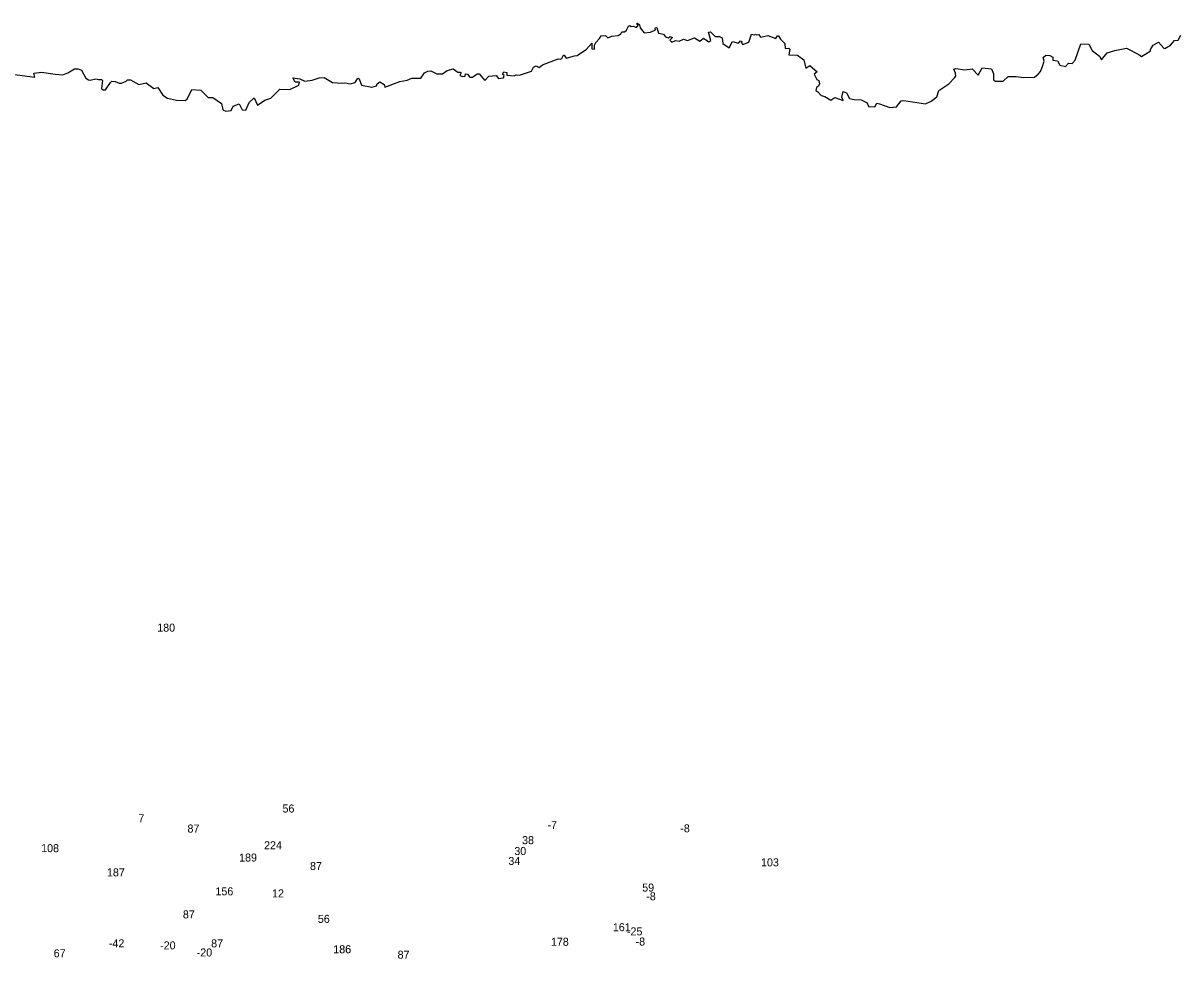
# Model space of a CAD drawing. Extents: x -788870 to -783053, y -967261 to -964403.
# Drawn here: x -787389 to -785943, y -965596 to -964427 of the extents above; entities that cross this region are included whole.
import ezdxf

# ---------------------------------------------------------------- set-up
doc = ezdxf.new("R2010")
doc.units = 0
doc.layers.add('Vrstva 13', color=7, linetype='Continuous')
doc.layers.add('Vrstva 15', color=7, linetype='Continuous')

msp = doc.modelspace()

# ---------------------------------------------------------------- linework, layer by layer
at = {"layer": 'Vrstva 13'}
for p, q in [((-786635.28, -964435.87), (-786632.81, -964430.8)), ((-786632.81, -964430.8), (-786631.37, -964429.93)), ((-786631.37, -964429.93), (-786629.34, -964431.52)), ((-786629.34, -964431.52), (-786626.44, -964430.73)), ((-786626.44, -964430.73), (-786622.68, -964432.68)), ((-786622.75, -964428.19), (-786621.52, -964427.18)), ((-786620.94, -964429.71), (-786622.75, -964428.19)), ((-786622.68, -964432.68), (-786620.94, -964429.71)), ((-786621.52, -964427.18), (-786618.91, -964429.35)), ((-786618.91, -964429.35), (-786618.26, -964432.9)), ((-786673.52, -964451.3), (-786669.1, -964446.23)), ((-786669.1, -964446.23), (-786666.78, -964443.04)), ((-786666.78, -964443.04), (-786661.71, -964442.39)), ((-786661.71, -964442.39), (-786658.46, -964445.57)), ((-786658.46, -964445.57), (-786653.75, -964443.4)), ((-786653.75, -964443.4), (-786645.64, -964442.46)), ((-786645.64, -964442.46), (-786642.24, -964440.5)), ((-786642.24, -964440.5), (-786641.37, -964437.82)), ((-786641.37, -964437.82), (-786637.81, -964437.82)), ((-786637.81, -964437.82), (-786635.28, -964435.87)), ((-786618.26, -964432.9), (-786613.26, -964439.2)), ((-786613.26, -964439.2), (-786605.15, -964438.33)), ((-786605.15, -964438.33), (-786599.14, -964435.51)), ((-786599.65, -964433.04), (-786597.33, -964432.46)), ((-786599.14, -964435.51), (-786599.65, -964433.04)), ((-786597.33, -964432.46), (-786595.16, -964439.85)), ((-786595.16, -964439.85), (-786589.29, -964440.72)), ((-786589.29, -964440.72), (-786586.69, -964444.13)), ((-786586.69, -964444.13), (-786582.85, -964445.65)), ((-786582.85, -964445.65), (-786580.67, -964443.91)), ((-786578, -964444.92), (-786581.33, -964448.33)), ((-786580.67, -964443.91), (-786578, -964444.92)), ((-786559.1, -964448.91), (-786550.26, -964445.51)), ((-786550.26, -964445.51), (-786543.82, -964449.56)), ((-786543.82, -964449.56), (-786539.11, -964445.94)), ((-786539.11, -964445.94), (-786532.52, -964450.43)), ((-786533.1, -964438.55), (-786530.42, -964438.04)), ((-786529.91, -964448.84), (-786533.1, -964438.55)), ((-786530.42, -964438.04), (-786524.41, -964443.98)), ((-786524.41, -964443.98), (-786519.05, -964443.98)), ((-786519.05, -964443.98), (-786516.01, -964445.29)), ((-786516.01, -964445.29), (-786514.85, -964452.68)), ((-786482.33, -964451.09), (-786479, -964440.8)), ((-786479, -964440.8), (-786475.67, -964441.6)), ((-786475.67, -964441.6), (-786473.86, -964440.73)), ((-786473.86, -964440.73), (-786473.5, -964441.74)), ((-786473.5, -964441.74), (-786470.09, -964441.16)), ((-786470.09, -964441.16), (-786468.07, -964444.78)), ((-786468.07, -964444.78), (-786458.94, -964442.39)), ((-786458.94, -964442.39), (-786448.73, -964446.38)), ((-786448.73, -964446.38), (-786446.85, -964442.9)), ((-786446.85, -964442.9), (-786445.33, -964442.9)), ((-786445.33, -964442.9), (-786442.94, -964447.32)), ((-785946.35, -964448.35), (-785942.82, -964442.17)), ((-786697.13, -964467.59), (-786685.25, -964459.7)), ((-786685.25, -964459.7), (-786678.81, -964452.02)), ((-786678.81, -964452.02), (-786678.74, -964459.33)), ((-786678.74, -964459.33), (-786675.48, -964459.77)), ((-786675.48, -964459.77), (-786675.47, -964454.85)), ((-786675.47, -964454.85), (-786673.52, -964451.3)), ((-786581.33, -964448.33), (-786578.5, -964450.86)), ((-786578.5, -964450.86), (-786574.02, -964448.69)), ((-786574.02, -964448.69), (-786569.53, -964449.49)), ((-786569.53, -964449.49), (-786564.1, -964447.32)), ((-786564.1, -964447.32), (-786559.1, -964448.91)), ((-786532.52, -964450.43), (-786529.91, -964448.84)), ((-786514.85, -964452.68), (-786507.24, -964457.96)), ((-786507.24, -964457.96), (-786502.83, -964449.99)), ((-786502.83, -964449.99), (-786495.37, -964452.1)), ((-786495.37, -964452.1), (-786492.76, -964449.21)), ((-786492.76, -964449.21), (-786491.17, -964450.07)), ((-786491.17, -964450.07), (-786492.04, -964451.52)), ((-786492.04, -964451.52), (-786490.15, -964453.99)), ((-786490.15, -964453.99), (-786482.33, -964451.09)), ((-786442.94, -964447.32), (-786437.72, -964452.39)), ((-786437.72, -964452.39), (-786437.22, -964458.98)), ((-786437.22, -964458.98), (-786432.73, -964458.26)), ((-786432.73, -964458.26), (-786431.28, -964459.49)), ((-786431.28, -964459.49), (-786432.72, -964466.74)), ((-786074.99, -964473.33), (-786067.74, -964453.19)), ((-786067.74, -964453.19), (-786057.75, -964453.61)), ((-786057.75, -964453.61), (-786053.69, -964461.15)), ((-786025.3, -964461.15), (-786010.82, -964458.54)), ((-786010.82, -964458.54), (-785995.18, -964466.36)), ((-785981.23, -964462.26), (-785980.13, -964459.17)), ((-785980.13, -964459.17), (-785977.48, -964454.75)), ((-785977.48, -964454.75), (-785970.63, -964451)), ((-785970.63, -964451), (-785964.23, -964458.51)), ((-785964.23, -964458.51), (-785962.91, -964458.95)), ((-785962.91, -964458.95), (-785955.84, -964454.75)), ((-785955.84, -964454.75), (-785950.77, -964448.79)), ((-785950.77, -964448.79), (-785946.35, -964448.35)), ((-786740.44, -964479.39), (-786720.52, -964471.79)), ((-786720.52, -964471.79), (-786717.77, -964472.16)), ((-786717.77, -964472.16), (-786716.03, -964471.14)), ((-786716.03, -964471.14), (-786714.07, -964467.09)), ((-786714.07, -964467.09), (-786713.21, -964467.23)), ((-786713.21, -964467.23), (-786710.82, -964470.78)), ((-786710.82, -964470.78), (-786700.39, -964467.81)), ((-786700.39, -964467.81), (-786697.13, -964467.59)), ((-786432.72, -964466.74), (-786421.64, -964466.96)), ((-786421.64, -964466.96), (-786413.89, -964472.97)), ((-786413.89, -964472.97), (-786411.5, -964483.18)), ((-786115.54, -964481.45), (-786113.66, -964474.64)), ((-786114.82, -964470.15), (-786111.34, -964466.96)), ((-786113.66, -964474.64), (-786114.82, -964470.15)), ((-786111.34, -964466.96), (-786106.42, -964467.39)), ((-786106.42, -964467.39), (-786102.8, -964469.71)), ((-786102.8, -964469.71), (-786102.8, -964473.48)), ((-786102.8, -964473.48), (-786096.86, -964474.35)), ((-786096.86, -964474.35), (-786093.82, -964479.42)), ((-786078.46, -964477.38), (-786074.99, -964473.33)), ((-786053.69, -964461.15), (-786044.42, -964468.39)), ((-786044.42, -964468.39), (-786041.82, -964473.03)), ((-786041.82, -964473.03), (-786034.86, -964464.34)), ((-786034.86, -964464.34), (-786025.3, -964461.15)), ((-785995.18, -964466.36), (-785991.99, -964468.97)), ((-785991.99, -964468.97), (-785981.23, -964462.26)), ((-787375.53, -964489.54), (-787365.83, -964488.23)), ((-787374.37, -964494.75), (-787375.53, -964489.54)), ((-787365.83, -964488.23), (-787358.01, -964489.54)), ((-787358.01, -964489.54), (-787349.03, -964490.84)), ((-787339.32, -964491.71), (-787333.24, -964489.39)), ((-787333.24, -964489.39), (-787324.98, -964484.32)), ((-787324.98, -964484.32), (-787320.35, -964484.18)), ((-787320.35, -964484.18), (-787316.15, -964485.92)), ((-787316.15, -964485.92), (-787310.65, -964495.77)), ((-786892.23, -964495.76), (-786887.88, -964489.39)), ((-786887.88, -964489.39), (-786883.39, -964487.21)), ((-786883.39, -964487.21), (-786879.77, -964486.63)), ((-786879.77, -964486.63), (-786872.24, -964490.25)), ((-786865.28, -964490.26), (-786859.34, -964486.2)), ((-786859.34, -964486.2), (-786851.67, -964484.17)), ((-786851.67, -964484.17), (-786849.06, -964486.49)), ((-786849.06, -964486.49), (-786846.16, -964488.38)), ((-786846.16, -964488.38), (-786843.27, -964488.38)), ((-786841.96, -964489.24), (-786843.41, -964492.43)), ((-786843.27, -964488.38), (-786841.96, -964489.24)), ((-786790.41, -964490.84), (-786788.52, -964487.8)), ((-786788.52, -964487.8), (-786784.9, -964488.66)), ((-786784.9, -964488.66), (-786784.68, -964492)), ((-786768.97, -964492.29), (-786754.05, -964486.93)), ((-786754.05, -964486.93), (-786751.66, -964482.15)), ((-786751.66, -964482.15), (-786748.19, -964480.26)), ((-786748.19, -964480.26), (-786744.57, -964482.58)), ((-786744.57, -964482.58), (-786740.44, -964479.39)), ((-786411.5, -964483.18), (-786406.29, -964479.92)), ((-786406.29, -964479.92), (-786396.95, -964487.75)), ((-786396.95, -964487.75), (-786401, -964490.86)), ((-786226.49, -964484.63), (-786223.88, -964483.91)), ((-786224.31, -964489.56), (-786226.49, -964484.63)), ((-786223.88, -964493.32), (-786224.31, -964489.56)), ((-786223.88, -964483.91), (-786212.58, -964485.36)), ((-786212.58, -964485.36), (-786203.46, -964484.2)), ((-786203.46, -964484.2), (-786196.22, -964492.31)), ((-786196.22, -964492.31), (-786191, -964482.89)), ((-786191, -964482.89), (-786179.41, -964484.2)), ((-786179.41, -964484.2), (-786176.95, -964490.57)), ((-786121.04, -964490.72), (-786118.15, -964487.39)), ((-786118.15, -964487.39), (-786115.54, -964481.45)), ((-786093.82, -964479.42), (-786086.72, -964481.16)), ((-786086.72, -964481.16), (-786083.1, -964476.95)), ((-786083.1, -964476.95), (-786078.46, -964477.38)), ((-787402.61, -964490.99), (-787374.37, -964494.75)), ((-787349.03, -964490.84), (-787339.32, -964491.71)), ((-787310.65, -964495.77), (-787307.6, -964497.8)), ((-787307.6, -964497.8), (-787305.43, -964498.23)), ((-787305.43, -964498.23), (-787298.48, -964496.49)), ((-787298.48, -964496.49), (-787295, -964497.65)), ((-787295, -964497.65), (-787291.24, -964497.65)), ((-787289.79, -964498.95), (-787291.38, -964508.66)), ((-787291.24, -964497.65), (-787289.79, -964498.95)), ((-787286.17, -964510.4), (-787280.09, -964501.13)), ((-787280.09, -964501.13), (-787278.2, -964499.53)), ((-787278.2, -964499.53), (-787274.29, -964500.11)), ((-787274.29, -964500.11), (-787268.93, -964502)), ((-787268.93, -964502), (-787266.04, -964502.29)), ((-787266.04, -964502.29), (-787260.53, -964499.53)), ((-787260.53, -964499.53), (-787258.65, -964497.94)), ((-787258.65, -964497.94), (-787255.03, -964498.08)), ((-787255.03, -964498.08), (-787244.46, -964503.88)), ((-787244.46, -964503.88), (-787235.48, -964501.71)), ((-787235.48, -964501.71), (-787225.92, -964508.66)), ((-787049.37, -964500.68), (-787052.26, -964495.32)), ((-787052.26, -964495.32), (-787043.28, -964496.77)), ((-787043.72, -964500.83), (-787049.37, -964500.68)), ((-787044.88, -964504.74), (-787043.72, -964500.83)), ((-787043.28, -964496.77), (-787037.35, -964499.52)), ((-787037.35, -964499.52), (-787028.08, -964498.36)), ((-787028.08, -964498.36), (-787019.1, -964495.61)), ((-787019.1, -964495.61), (-787013.16, -964495.18)), ((-787013.16, -964495.18), (-787002.73, -964501.26)), ((-787002.73, -964501.26), (-786990.28, -964502.13)), ((-786990.28, -964502.13), (-786986.37, -964501.55)), ((-786986.37, -964501.55), (-786980.58, -964503)), ((-786980.58, -964503), (-786974.2, -964501.12)), ((-786974.2, -964501.12), (-786971.16, -964495.9)), ((-786971.16, -964495.9), (-786969.13, -964496.77)), ((-786969.13, -964496.77), (-786966.24, -964504.45)), ((-786947.84, -964505.32), (-786946.97, -964503.14)), ((-786946.97, -964503.14), (-786943.64, -964500.25)), ((-786943.64, -964500.25), (-786938.28, -964503.87)), ((-786938.28, -964503.87), (-786937.13, -964507.21)), ((-786937.13, -964507.21), (-786918.3, -964500.11)), ((-786918.3, -964500.11), (-786909.32, -964498.51)), ((-786909.32, -964498.51), (-786903.38, -964495.76)), ((-786903.38, -964495.76), (-786892.23, -964495.76)), ((-786872.24, -964490.25), (-786865.28, -964490.26)), ((-786843.41, -964492.43), (-786839.79, -964493.88)), ((-786839.79, -964493.88), (-786836.9, -964493.45)), ((-786836.9, -964493.45), (-786836.46, -964490.4)), ((-786836.46, -964490.4), (-786834.14, -964490.84)), ((-786834.14, -964490.84), (-786831.25, -964494.46)), ((-786831.25, -964494.46), (-786827.63, -964494.61)), ((-786827.63, -964494.61), (-786821.69, -964490.55)), ((-786821.69, -964490.55), (-786819.23, -964490.4)), ((-786819.23, -964490.4), (-786812.49, -964498.81)), ((-786812.49, -964498.81), (-786807.35, -964493.3)), ((-786807.35, -964493.3), (-786798.23, -964492.58)), ((-786798.23, -964492.58), (-786795.33, -964496.34)), ((-786795.33, -964496.34), (-786788.96, -964495.62)), ((-786788.16, -964492.51), (-786790.41, -964490.84)), ((-786788.96, -964495.62), (-786788.16, -964492.51)), ((-786784.68, -964492), (-786775.78, -964493.09)), ((-786775.78, -964493.09), (-786773.1, -964491.85)), ((-786773.1, -964491.85), (-786768.97, -964492.29)), ((-786401, -964490.86), (-786397.38, -964497.68)), ((-786397.38, -964497.68), (-786394.92, -964498.84)), ((-786394.05, -964502.75), (-786395.64, -964505.65)), ((-786394.92, -964498.84), (-786394.05, -964502.75)), ((-786245.02, -964511.29), (-786232.71, -964502.74)), ((-786232.71, -964502.74), (-786225.62, -964495.5)), ((-786225.62, -964495.5), (-786223.88, -964493.32)), ((-786176.95, -964490.57), (-786176.66, -964498.11)), ((-786176.66, -964498.11), (-786174.49, -964499.55)), ((-786174.49, -964499.55), (-786171.01, -964499.55)), ((-786171.01, -964499.55), (-786164.64, -964499.41)), ((-786164.64, -964499.41), (-786158.41, -964493.91)), ((-786158.41, -964493.91), (-786148.42, -964493.91)), ((-786148.42, -964493.91), (-786139.44, -964495.07)), ((-786139.44, -964495.07), (-786125.82, -964494.63)), ((-786125.82, -964494.63), (-786121.04, -964490.72)), ((-787291.38, -964508.66), (-787289.21, -964510.4)), ((-787289.21, -964510.4), (-787286.17, -964510.4)), ((-787225.92, -964508.66), (-787220.85, -964507.5)), ((-787220.85, -964507.5), (-787214.48, -964516.92)), ((-787214.48, -964516.92), (-787208.83, -964520.83)), ((-787184.06, -964521.99), (-787178.41, -964509.96)), ((-787178.41, -964509.96), (-787167.26, -964510.69)), ((-787167.26, -964510.69), (-787157.99, -964520.1)), ((-787079.78, -964520.97), (-787068.48, -964509.66)), ((-787068.48, -964509.66), (-787055.74, -964509.95)), ((-787055.74, -964509.95), (-787044.88, -964504.74)), ((-786966.24, -964504.45), (-786953.64, -964506.91)), ((-786953.64, -964506.91), (-786947.84, -964505.32)), ((-786397.81, -964507.53), (-786398.68, -964511.15)), ((-786398.68, -964511.15), (-786396.51, -964513.04)), ((-786395.64, -964505.65), (-786397.81, -964507.53)), ((-786396.51, -964513.04), (-786392.17, -964517.53)), ((-786392.17, -964517.53), (-786387.68, -964518.69)), ((-786366.39, -964519.41), (-786364.79, -964512.46)), ((-786364.79, -964512.46), (-786360.59, -964514.34)), ((-786360.59, -964514.34), (-786356.68, -964521.29)), ((-786247.63, -964519.11), (-786245.02, -964511.29)), ((-787208.83, -964520.83), (-787197.67, -964523.29)), ((-787197.67, -964523.29), (-787186.81, -964523.73)), ((-787186.81, -964523.73), (-787184.06, -964521.99)), ((-787157.99, -964520.1), (-787152.05, -964519.96)), ((-787152.05, -964519.96), (-787141.33, -964527.64)), ((-787141.33, -964527.64), (-787139.59, -964535.46)), ((-787129.31, -964536.33), (-787126.56, -964530.97)), ((-787126.56, -964530.97), (-787119.03, -964528.07)), ((-787119.03, -964528.07), (-787115.55, -964535.32)), ((-787110.92, -964535.9), (-787106.57, -964526.19)), ((-787106.57, -964526.19), (-787100.49, -964520.39)), ((-787100.49, -964520.39), (-787096.43, -964529.52)), ((-787096.43, -964529.52), (-787087.17, -964523.43)), ((-787087.17, -964523.43), (-787079.78, -964520.97)), ((-786387.68, -964518.69), (-786380, -964523.32)), ((-786380, -964523.32), (-786375.08, -964519.99)), ((-786375.08, -964519.99), (-786364.79, -964523.61)), ((-786364.79, -964523.61), (-786366.39, -964519.41)), ((-786356.68, -964521.29), (-786350.89, -964522.6)), ((-786350.89, -964522.6), (-786342.34, -964522.89)), ((-786342.34, -964522.89), (-786334.81, -964526.65)), ((-786334.81, -964526.65), (-786333.07, -964531.29)), ((-786333.07, -964531.29), (-786325.11, -964531.58)), ((-786325.11, -964531.58), (-786322.8, -964527.23)), ((-786322.8, -964527.23), (-786319.46, -964527.81)), ((-786319.46, -964527.81), (-786306.29, -964532.3)), ((-786306.29, -964532.3), (-786298.17, -964531.72)), ((-786298.17, -964531.72), (-786292.24, -964524.18)), ((-786292.24, -964524.18), (-786289.05, -964523.75)), ((-786289.05, -964523.75), (-786261.97, -964527.81)), ((-786261.97, -964527.81), (-786254.72, -964524.47)), ((-786254.72, -964524.47), (-786247.63, -964519.11)), ((-787139.59, -964535.46), (-787135.83, -964537.05)), ((-787135.83, -964537.05), (-787129.31, -964536.33)), ((-787115.55, -964535.32), (-787110.92, -964535.9))]:
    msp.add_line(p, q, dxfattribs=at)

# ---------------------------------------------------------------- texts
at = {"layer": 'Vrstva 15'}
for s, p in [('180', (-787221.611, -965186.98)), ('7', (-787245.156, -965424.99)), ('56', (-787065.09, -965412.79)), ('87', (-787183.796, -965437.81)), ('-7', (-786734.059, -965433.28)), ('-8', (-786568.16, -965437.55)), ('38', (-786765.816, -965452.32)), ('108', (-787366.58, -965462.31)), ('224', (-787088.112, -965458.66)), ('30', (-786775.476, -965465.9)), ('189', (-787119.324, -965474.03)), ('34', (-786782.892, -965478.28)), ('103', (-786467.27, -965480.02)), ('187', (-787284.37, -965492.57)), ('87', (-787030.716, -965484.59)), ('59', (-786615.71, -965511.51)), ('156', (-787148.864, -965516.19)), ('12', (-787078.131, -965518.76)), ('-8', (-786610.68, -965522.41)), ('87', (-787189.536, -965545.05)), ('56', (-787020.94, -965550.61)), ('161', (-786652.388, -965561.01)), ('-25', (-786634.81, -965566.23)), ('-42', (-787281.996, -965581.16)), ('-20', (-787217.94, -965583.72)), ('87', (-787154.236, -965581.24)), ('178', (-786729.79, -965579.2)), ('-8', (-786623.98, -965578.92)), ('67', (-787350.928, -965593.59)), ('-20', (-787172.25, -965592.55)), ('186', (-787001.754, -965588.55)), ('186', (-787001.534, -965588.55)), ('87', (-786921.306, -965595.36))]:
    msp.add_text(s, height=10, dxfattribs=at).set_placement(p)

doc.saveas('drawing.dxf')
